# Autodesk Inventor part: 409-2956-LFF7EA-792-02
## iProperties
Shininess: 64.0
Angle Display Precision: 2
Document Length Units: 11272
Document Angle Units: 11279
Document Time Units: 11290
Document Mass Units: 11286
Document Length Units Precision: 3
Document Angle Units Precision: 2
Compacted: True
Created: 2002-04
Part Number: 409-2956-LFF7EA-792-02
Description: 2" PIPE MOUNT ANGLE
Document SubType Name: Modeling
Designer: S. Boerckel
Mass: 1123.41 g
Surface Area: 473.124 cm^2
Volume: 139.902 cm^3
Density: 8.03 g/cm^3
Cost Center: 3 x 3 x 1/4 ANGLE
Material: STAINLESS STEEL, 304
Engineer: S. Boerckel
User Status: SAW/PUNCH
Density: 0.0
Volumn: 0.0
Area: 0.0
PropertySet Name: Model Information
Control State: 0
Master: False
Checked Out: False
length: 6.000 in
SMR: =<COST CENTER> - <MATERIAL>
Author: S. Boerckel
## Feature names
1. Extrusion1
2. Hole1
